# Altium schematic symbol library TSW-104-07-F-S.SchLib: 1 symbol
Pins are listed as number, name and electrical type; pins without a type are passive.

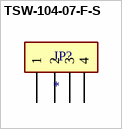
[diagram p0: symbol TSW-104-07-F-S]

## TSW-104-07-F-S
designator JP?
Connector Header Through Hole 4 position 0.100 (2.54mm); MP: TSW-104-24-G-S; MF: Samtec
footprint TSW-104-07-F-S
pins: 1, 2, 3, 4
